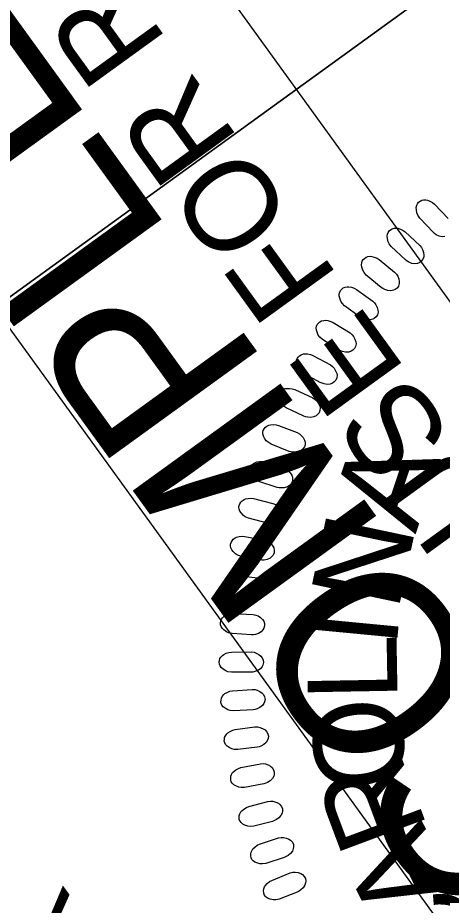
# Model space of a CAD drawing. Extents: x 474925 to 478950, y 494687 to 502905.
# Drawn here: x 475070.1 to 475096.9, y 502185.1 to 502241.2 of the extents above; entities that cross this region are included whole.
import ezdxf

# ---------------------------------------------------------------- set-up
doc = ezdxf.new("R2010")
doc.units = 0
for name, color, linetype in [('Sheet PE Seal Cell', 7, 'Continuous'), ('Sheet Plan CELL', 7, 'Continuous'), ('Sheet Sticker Incomplete CELL', 7, 'Continuous')]:
    doc.layers.add(name, color=color, linetype=linetype)

msp = doc.modelspace()

# ---------------------------------------------------------------- linework, layer by layer
at = {"layer": 'Sheet PE Seal Cell'}
msp.add_lwpolyline([(475097.086, 502227.355), (475096.925, 502227.341), (475096.722, 502227.383), (475096.551, 502227.468), (475096.44, 502227.543), (475096.341, 502227.627), (475095.503, 502228.523), (475095.38, 502228.708), (475095.323, 502228.846), (475095.289, 502229.046), (475095.285, 502229.193), (475095.312, 502229.328), (475095.361, 502229.428), (475095.43, 502229.519), (475095.525, 502229.581), (475095.633, 502229.641), (475095.751, 502229.67), (475095.895, 502229.668), (475095.993, 502229.65), (475096.145, 502229.587), (475096.311, 502229.497), (475096.437, 502229.396), (475097.3, 502228.483)], dxfattribs=at)
for points in [[(475094.598, 502225.874), (475093.706, 502226.715), (475093.572, 502226.893), (475093.506, 502227.026), (475093.46, 502227.225), (475093.447, 502227.37), (475093.465, 502227.507), (475093.508, 502227.61), (475093.57, 502227.706), (475093.662, 502227.773), (475093.766, 502227.84), (475093.881, 502227.875), (475094.025, 502227.883), (475094.124, 502227.872), (475094.28, 502227.818), (475094.451, 502227.738), (475094.583, 502227.645), (475095.503, 502226.789), (475095.61, 502226.656), (475095.681, 502226.528), (475095.735, 502226.353), (475095.76, 502226.176), (475095.752, 502226.05), (475095.688, 502225.894), (475095.599, 502225.772), (475095.468, 502225.691), (475095.36, 502225.649), (475095.2, 502225.625), (475094.995, 502225.654), (475094.817, 502225.729), (475094.703, 502225.796)], [(475093.072, 502224.139), (475092.128, 502224.923), (475091.984, 502225.091), (475091.909, 502225.221), (475091.85, 502225.416), (475091.828, 502225.56), (475091.838, 502225.698), (475091.874, 502225.803), (475091.931, 502225.902), (475092.018, 502225.976), (475092.118, 502226.049), (475092.229, 502226.091), (475092.373, 502226.108), (475092.473, 502226.103), (475092.631, 502226.059), (475092.808, 502225.99), (475092.945, 502225.906), (475093.916, 502225.109), (475094.032, 502224.983), (475094.111, 502224.859), (475094.176, 502224.688), (475094.212, 502224.513), (475094.212, 502224.387), (475094.157, 502224.228), (475094.077, 502224.101), (475093.951, 502224.011), (475093.846, 502223.963), (475093.688, 502223.929), (475093.481, 502223.945), (475093.3, 502224.008), (475093.181, 502224.068)], [(475091.749, 502222.261), (475090.757, 502222.984), (475090.602, 502223.144), (475090.52, 502223.268), (475090.449, 502223.459), (475090.417, 502223.602), (475090.419, 502223.74), (475090.449, 502223.847), (475090.499, 502223.95), (475090.581, 502224.029), (475090.676, 502224.108), (475090.785, 502224.157), (475090.928, 502224.182), (475091.027, 502224.184), (475091.189, 502224.15), (475091.368, 502224.093), (475091.511, 502224.017), (475092.531, 502223.282), (475092.654, 502223.164), (475092.74, 502223.045), (475092.816, 502222.879), (475092.863, 502222.707), (475092.87, 502222.581), (475092.826, 502222.418), (475092.754, 502222.286), (475092.633, 502222.189), (475092.532, 502222.134), (475092.376, 502222.09), (475092.169, 502222.093), (475091.984, 502222.144), (475091.862, 502222.197)], [(475090.387, 502220.196), (475089.352, 502220.855), (475089.187, 502221.005), (475089.097, 502221.123), (475089.015, 502221.309), (475088.975, 502221.45), (475088.968, 502221.588), (475088.99, 502221.697), (475089.034, 502221.803), (475089.111, 502221.886), (475089.2, 502221.971), (475089.307, 502222.027), (475089.448, 502222.062), (475089.547, 502222.07), (475089.709, 502222.046), (475089.893, 502222), (475090.039, 502221.933), (475091.103, 502221.264), (475091.234, 502221.154), (475091.327, 502221.041), (475091.414, 502220.88), (475091.471, 502220.71), (475091.486, 502220.585), (475091.452, 502220.42), (475091.389, 502220.284), (475091.275, 502220.179), (475091.176, 502220.118), (475091.024, 502220.064), (475090.817, 502220.055), (475090.629, 502220.094), (475090.504, 502220.139)], [(475089.211, 502218.135), (475088.137, 502218.728), (475087.963, 502218.867), (475087.866, 502218.98), (475087.772, 502219.16), (475087.723, 502219.298), (475087.707, 502219.435), (475087.723, 502219.546), (475087.759, 502219.654), (475087.831, 502219.742), (475087.915, 502219.832), (475088.018, 502219.895), (475088.156, 502219.939), (475088.255, 502219.952), (475088.419, 502219.939), (475088.604, 502219.904), (475088.755, 502219.847), (475089.859, 502219.246), (475089.996, 502219.144), (475090.096, 502219.037), (475090.192, 502218.882), (475090.261, 502218.716), (475090.284, 502218.593), (475090.26, 502218.426), (475090.205, 502218.285), (475090.098, 502218.174), (475090.003, 502218.107), (475089.855, 502218.043), (475089.649, 502218.021), (475089.459, 502218.049), (475089.331, 502218.086)], [(475088.173, 502216.016), (475087.064, 502216.541), (475086.882, 502216.669), (475086.777, 502216.775), (475086.672, 502216.949), (475086.615, 502217.084), (475086.591, 502217.22), (475086.6, 502217.331), (475086.629, 502217.441), (475086.695, 502217.534), (475086.773, 502217.629), (475086.872, 502217.698), (475087.007, 502217.75), (475087.104, 502217.77), (475087.269, 502217.767), (475087.456, 502217.744), (475087.61, 502217.696), (475088.749, 502217.166), (475088.893, 502217.073), (475089, 502216.973), (475089.106, 502216.823), (475089.184, 502216.663), (475089.215, 502216.54), (475089.202, 502216.373), (475089.156, 502216.229), (475089.056, 502216.111), (475088.966, 502216.038), (475088.822, 502215.965), (475088.617, 502215.93), (475088.426, 502215.946), (475088.296, 502215.975)], [(475087.252, 502213.793), (475086.112, 502214.246), (475085.922, 502214.363), (475085.812, 502214.463), (475085.696, 502214.629), (475085.63, 502214.761), (475085.597, 502214.894), (475085.599, 502215.006), (475085.622, 502215.118), (475085.682, 502215.214), (475085.754, 502215.315), (475085.848, 502215.389), (475085.98, 502215.45), (475086.076, 502215.476), (475086.24, 502215.483), (475086.429, 502215.472), (475086.585, 502215.434), (475087.755, 502214.977), (475087.904, 502214.893), (475088.017, 502214.799), (475088.133, 502214.657), (475088.221, 502214.501), (475088.259, 502214.381), (475088.257, 502214.213), (475088.22, 502214.067), (475088.128, 502213.943), (475088.043, 502213.864), (475087.902, 502213.783), (475087.701, 502213.734), (475087.509, 502213.739), (475087.378, 502213.759)], [(475086.497, 502211.517), (475085.331, 502211.899), (475085.135, 502212.002), (475085.018, 502212.095), (475084.891, 502212.255), (475084.818, 502212.381), (475084.777, 502212.512), (475084.771, 502212.624), (475084.787, 502212.737), (475084.841, 502212.838), (475084.906, 502212.942), (475084.996, 502213.023), (475085.123, 502213.091), (475085.218, 502213.123), (475085.381, 502213.141), (475085.57, 502213.142), (475085.729, 502213.114), (475086.925, 502212.73), (475087.079, 502212.656), (475087.199, 502212.57), (475087.322, 502212.435), (475087.42, 502212.285), (475087.466, 502212.168), (475087.474, 502212), (475087.446, 502211.851), (475087.362, 502211.722), (475087.282, 502211.638), (475087.147, 502211.548), (475086.949, 502211.487), (475086.758, 502211.479), (475086.625, 502211.491)], [(475085.878, 502209.265), (475084.69, 502209.573), (475084.487, 502209.664), (475084.365, 502209.75), (475084.229, 502209.901), (475084.147, 502210.023), (475084.098, 502210.151), (475084.085, 502210.262), (475084.094, 502210.376), (475084.142, 502210.479), (475084.201, 502210.588), (475084.285, 502210.674), (475084.407, 502210.75), (475084.5, 502210.788), (475084.662, 502210.816), (475084.85, 502210.828), (475085.01, 502210.811), (475086.229, 502210.503), (475086.387, 502210.439), (475086.511, 502210.36), (475086.643, 502210.233), (475086.75, 502210.09), (475086.803, 502209.976), (475086.822, 502209.809), (475086.803, 502209.659), (475086.727, 502209.525), (475086.653, 502209.436), (475086.525, 502209.337), (475086.331, 502209.264), (475086.14, 502209.244), (475086.007, 502209.248)], [(475085.408, 502206.936), (475084.204, 502207.168), (475083.996, 502207.246), (475083.868, 502207.324), (475083.723, 502207.466), (475083.634, 502207.582), (475083.577, 502207.707), (475083.557, 502207.818), (475083.559, 502207.932), (475083.6, 502208.038), (475083.652, 502208.15), (475083.73, 502208.241), (475083.848, 502208.325), (475083.938, 502208.369), (475084.097, 502208.406), (475084.285, 502208.431), (475084.446, 502208.423), (475085.681, 502208.192), (475085.843, 502208.138), (475085.972, 502208.068), (475086.111, 502207.95), (475086.227, 502207.813), (475086.288, 502207.702), (475086.317, 502207.537), (475086.308, 502207.386), (475086.241, 502207.247), (475086.172, 502207.154), (475086.05, 502207.048), (475085.861, 502206.963), (475085.671, 502206.931), (475085.538, 502206.926)], [(475085.06, 502204.53), (475083.843, 502204.686), (475083.63, 502204.751), (475083.498, 502204.82), (475083.344, 502204.953), (475083.248, 502205.064), (475083.183, 502205.185), (475083.157, 502205.294), (475083.151, 502205.408), (475083.185, 502205.516), (475083.23, 502205.631), (475083.303, 502205.727), (475083.415, 502205.818), (475083.502, 502205.868), (475083.659, 502205.915), (475083.844, 502205.952), (475084.005, 502205.954), (475085.253, 502205.801), (475085.418, 502205.757), (475085.551, 502205.695), (475085.698, 502205.586), (475085.822, 502205.457), (475085.889, 502205.35), (475085.928, 502205.187), (475085.929, 502205.036), (475085.87, 502204.893), (475085.807, 502204.796), (475085.693, 502204.682), (475085.509, 502204.585), (475085.323, 502204.541), (475085.19, 502204.528)], [(475084.873, 502202.207), (475083.649, 502202.286), (475083.432, 502202.337), (475083.296, 502202.399), (475083.134, 502202.522), (475083.031, 502202.626), (475082.958, 502202.743), (475082.925, 502202.849), (475082.913, 502202.963), (475082.939, 502203.073), (475082.978, 502203.191), (475083.044, 502203.292), (475083.15, 502203.389), (475083.234, 502203.444), (475083.388, 502203.501), (475083.57, 502203.55), (475083.731, 502203.562), (475084.985, 502203.488), (475085.154, 502203.455), (475085.29, 502203.4), (475085.443, 502203.301), (475085.576, 502203.18), (475085.649, 502203.078), (475085.699, 502202.917), (475085.708, 502202.767), (475085.659, 502202.62), (475085.602, 502202.519), (475085.495, 502202.399), (475085.318, 502202.291), (475085.134, 502202.235), (475085.003, 502202.214)], [(475084.837, 502199.842), (475083.61, 502199.844), (475083.39, 502199.882), (475083.251, 502199.934), (475083.082, 502200.047), (475082.972, 502200.144), (475082.892, 502200.256), (475082.853, 502200.362), (475082.833, 502200.474), (475082.853, 502200.585), (475082.883, 502200.705), (475082.943, 502200.809), (475083.043, 502200.914), (475083.123, 502200.974), (475083.273, 502201.041), (475083.452, 502201.1), (475083.612, 502201.122), (475084.869, 502201.127), (475085.038, 502201.104), (475085.178, 502201.059), (475085.337, 502200.97), (475085.477, 502200.857), (475085.556, 502200.759), (475085.616, 502200.603), (475085.635, 502200.453), (475085.595, 502200.303), (475085.545, 502200.199), (475085.445, 502200.072), (475085.275, 502199.953), (475085.096, 502199.886), (475084.966, 502199.856)], [(475084.978, 502197.475), (475083.754, 502197.401), (475083.532, 502197.424), (475083.39, 502197.468), (475083.214, 502197.57), (475083.098, 502197.66), (475083.012, 502197.767), (475082.966, 502197.869), (475082.939, 502197.98), (475082.952, 502198.093), (475082.975, 502198.214), (475083.028, 502198.322), (475083.121, 502198.433), (475083.197, 502198.497), (475083.343, 502198.574), (475083.518, 502198.644), (475083.676, 502198.677), (475084.93, 502198.76), (475085.1, 502198.748), (475085.242, 502198.712), (475085.407, 502198.632), (475085.553, 502198.529), (475085.639, 502198.437), (475085.709, 502198.284), (475085.737, 502198.135), (475085.707, 502197.984), (475085.663, 502197.876), (475085.572, 502197.743), (475085.41, 502197.614), (475085.234, 502197.536), (475085.106, 502197.498)], [(475085.225, 502195.113), (475084.008, 502194.962), (475083.786, 502194.972), (475083.641, 502195.006), (475083.459, 502195.097), (475083.338, 502195.18), (475083.245, 502195.281), (475083.192, 502195.38), (475083.159, 502195.489), (475083.165, 502195.603), (475083.18, 502195.725), (475083.226, 502195.836), (475083.312, 502195.952), (475083.384, 502196.022), (475083.524, 502196.107), (475083.695, 502196.188), (475083.85, 502196.231), (475085.097, 502196.393), (475085.267, 502196.391), (475085.412, 502196.364), (475085.581, 502196.295), (475085.733, 502196.201), (475085.825, 502196.114), (475085.903, 502195.966), (475085.942, 502195.82), (475085.921, 502195.667), (475085.884, 502195.556), (475085.8, 502195.418), (475085.647, 502195.279), (475085.477, 502195.19), (475085.352, 502195.144)], [(475085.649, 502192.797), (475084.443, 502192.57), (475084.221, 502192.566), (475084.074, 502192.591), (475083.886, 502192.67), (475083.761, 502192.745), (475083.662, 502192.841), (475083.603, 502192.936), (475083.562, 502193.043), (475083.562, 502193.157), (475083.568, 502193.28), (475083.608, 502193.394), (475083.687, 502193.515), (475083.754, 502193.588), (475083.889, 502193.682), (475084.054, 502193.774), (475084.206, 502193.826), (475085.44, 502194.067), (475085.61, 502194.076), (475085.756, 502194.058), (475085.93, 502193.999), (475086.088, 502193.915), (475086.184, 502193.834), (475086.272, 502193.691), (475086.319, 502193.547), (475086.308, 502193.394), (475086.278, 502193.282), (475086.204, 502193.138), (475086.059, 502192.989), (475085.895, 502192.89), (475085.774, 502192.837)], [(475086.207, 502190.434), (475085.018, 502190.132), (475084.796, 502190.114), (475084.648, 502190.13), (475084.456, 502190.197), (475084.325, 502190.264), (475084.22, 502190.353), (475084.156, 502190.444), (475084.109, 502190.548), (475084.101, 502190.661), (475084.1, 502190.785), (475084.133, 502190.901), (475084.203, 502191.027), (475084.266, 502191.105), (475084.394, 502191.207), (475084.553, 502191.309), (475084.702, 502191.37), (475085.918, 502191.688), (475086.088, 502191.707), (475086.235, 502191.699), (475086.411, 502191.651), (475086.574, 502191.577), (475086.676, 502191.503), (475086.772, 502191.365), (475086.828, 502191.225), (475086.827, 502191.071), (475086.804, 502190.957), (475086.739, 502190.809), (475086.604, 502190.652), (475086.447, 502190.541), (475086.328, 502190.481)], [(475086.951, 502188.154), (475085.783, 502187.777), (475085.562, 502187.745), (475085.414, 502187.752), (475085.218, 502187.807), (475085.084, 502187.866), (475084.973, 502187.948), (475084.903, 502188.035), (475084.85, 502188.136), (475084.835, 502188.248), (475084.827, 502188.372), (475084.851, 502188.49), (475084.914, 502188.619), (475084.971, 502188.701), (475085.093, 502188.811), (475085.245, 502188.923), (475085.39, 502188.994), (475086.584, 502189.386), (475086.752, 502189.418), (475086.899, 502189.418), (475087.079, 502189.382), (475087.246, 502189.317), (475087.351, 502189.25), (475087.457, 502189.118), (475087.521, 502188.982), (475087.529, 502188.828), (475087.514, 502188.713), (475087.458, 502188.561), (475087.334, 502188.396), (475087.184, 502188.276), (475087.069, 502188.208)], [(475087.766, 502185.967), (475086.625, 502185.517), (475086.407, 502185.472), (475086.258, 502185.469), (475086.059, 502185.511), (475085.921, 502185.561), (475085.806, 502185.637), (475085.731, 502185.719), (475085.67, 502185.817), (475085.648, 502185.928), (475085.632, 502186.051), (475085.65, 502186.17), (475085.704, 502186.303), (475085.756, 502186.388), (475085.871, 502186.506), (475086.016, 502186.627), (475086.157, 502186.707), (475087.323, 502187.174), (475087.489, 502187.215), (475087.635, 502187.224), (475087.817, 502187.199), (475087.988, 502187.146), (475088.098, 502187.085), (475088.211, 502186.961), (475088.284, 502186.829), (475088.301, 502186.675), (475088.294, 502186.56), (475088.247, 502186.405), (475088.134, 502186.231), (475087.991, 502186.103), (475087.882, 502186.028)]]:
    msp.add_lwpolyline(points, close=True, dxfattribs=at)
at = {"layer": 'Sheet Plan CELL'}
msp.add_line((475042.137, 502203.66), (475133.22, 502269.627), dxfattribs=at)
for points in [[(475042.137, 502203.66), (474983.486, 502284.639), (475074.61, 502350.635), (475133.268, 502269.646)], [(475100.814, 502122.623), (475042.137, 502203.66), (475133.268, 502269.646), (475191.917, 502188.605)]]:
    msp.add_lwpolyline(points, close=True, dxfattribs=at)
at = {"layer": 'Sheet Sticker Incomplete CELL'}
msp.add_lwpolyline([(475130.803, 502177.117), (475111.769, 502163.335), (475025.557, 502282.4), (475044.591, 502296.182)], close=True, dxfattribs=at)

# ---------------------------------------------------------------- texts
at = {"layer": 'Sheet PE Seal Cell'}
for s, rotation, p in [('A', 71.5802, (475095.236, 502208.532)), ('N', 78.0696, (475094.122, 502203.626)), ('I', 84.559, (475094.03, 502201.331)), ('L', 91.0483, (475094.108, 502198.063)), ('O', 97.5377, (475094.834, 502192.745)), ('R', 110.5164, (475096.037, 502189.968)), ('A', 117.0057, (475097.861, 502186.095)), ('C', 123.4951, (475100.376, 502182.267))]:
    msp.add_text(s, height=5.669, rotation=rotation, dxfattribs=at).set_placement(p)
at = {"layer": 'Sheet Plan CELL'}
for s, p in [('ROADWAY DESIGN', (475095.363, 502142.598)), ('ENGINEER', (475093.265, 502158.347))]:
    msp.add_text(s, height=5.0001, rotation=125.9074, dxfattribs=at).set_placement(p)
at = {"layer": 'Sheet Sticker Incomplete CELL'}
for s, height, p in [('INCOMPLETE PLANS', 11.52, (475116.078, 502177.504)), ('DO NOT USE FOR R/W ACQUISITION', 5.76, (475119.801, 502184.213))]:
    msp.add_text(s, height=height, rotation=125.9074, dxfattribs=at).set_placement(p)

doc.saveas('drawing.dxf')
